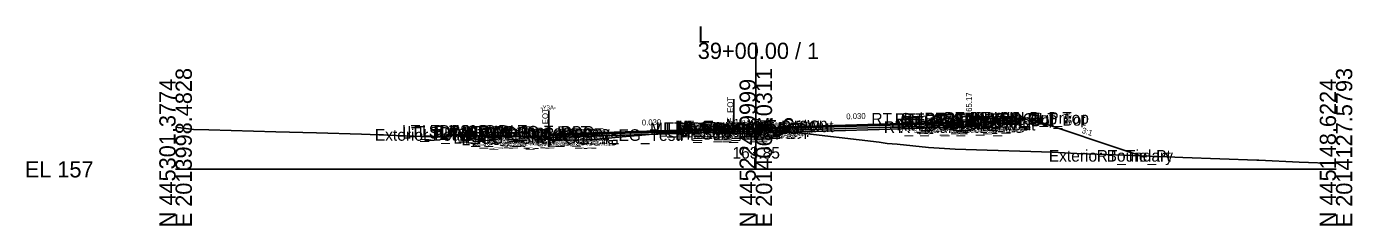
# Model space of a CAD drawing. Extents: x -26 to 4203, y -10 to 9526.
# Drawn here: x 1974.3 to 2202.8, y 8990.3 to 9024.6 of the extents above; entities that cross this region are included whole.
import ezdxf

# ---------------------------------------------------------------- set-up
doc = ezdxf.new("R2010")
doc.units = 0
for name, color, linetype in [('Default', 7, 'Continuous'), ('Exist CMT Pavement', 7, 'Continuous'), ('Exist Cross Section Cell', 7, 'Continuous'), ('Exist XS Center Line Elevation Label', 7, 'Continuous'), ('Exist XS Ground Line', 7, 'Continuous'), ('Prop CMT Conc Surface', 7, 'Continuous'), ('Prop CMT Concrete Structures', 7, 'Continuous'), ('Prop CMT Pvmt Course 1', 7, 'Continuous'), ('Prop CMT Pvmt Course 1 CG', 7, 'Continuous'), ('Prop CMT Pvmt Course 1 Wedge', 7, 'Continuous'), ('Prop CMT Pvmt Course 2', 7, 'Continuous'), ('Prop CMT Pvmt Course 2 Wedge', 7, 'Continuous'), ('Prop CMT Pvmt Course 3', 7, 'Continuous'), ('Prop CMT Pvmt Course 3 Wedge', 7, 'Continuous'), ('Prop CMT Pvmt Surface', 7, 'Continuous'), ('Prop CMT Pvmt Wedge Surface 1', 7, 'Continuous'), ('Prop CMT Pvmt Wedge Surface 2', 7, 'Continuous'), ('Prop CMT Pvmt Wedge Surface 3', 7, 'Continuous'), ('Prop CMT Shear Line', 7, 'Continuous'), ('Prop CMT Shear Line Text', 7, 'Continuous'), ('Prop CMT Slope Grass', 7, 'Continuous'), ('Prop CMT Subgrade Earthwork', 7, 'Continuous'), ('Prop XS Hydro Elevations', 7, 'Continuous'), ('Prop XS Label Text', 7, 'Continuous'), ('Prop XS SE Text', 7, 'Continuous'), ('Prop XS Side Slope Text', 7, 'Continuous'), ('Scratch_Level_0', 7, 'Continuous')]:
    doc.layers.add(name, color=color, linetype=linetype)

msp = doc.modelspace()

# ---------------------------------------------------------------- linework, layer by layer
at = {"layer": 'Exist CMT Pavement'}
for p, q in [((2086.78, 9006.43), (2090.05, 9006.68)), ((2090.05, 9006.68), (2090.65, 9006.73)), ((2090.65, 9006.73), (2092.1, 9006.81)), ((2092.1, 9006.81), (2093.35, 9006.9)), ((2093.35, 9006.9), (2094.49, 9006.97)), ((2094.49, 9006.97), (2095.82, 9007.06)), ((2095.82, 9007.06), (2096.21, 9007.08)), ((2064.31, 9005.13), (2068.53, 9005.01)), ((2068.53, 9005.01), (2069.19, 9005.04)), ((2069.19, 9005.04), (2072.26, 9005.15)), ((2072.26, 9005.15), (2076.98, 9005.61)), ((2076.98, 9005.61), (2079.7, 9005.86)), ((2079.7, 9005.86), (2082.91, 9006.13)), ((2082.91, 9006.13), (2084.39, 9006.25)), ((2084.39, 9006.25), (2086.78, 9006.43))]:
    msp.add_line(p, q, dxfattribs=at)
at = {"layer": 'Exist Cross Section Cell'}
for p, q in [((2100, 9000), (2100, 9021.84)), ((2000, 9000), (2100, 9000)), ((2100, 9000), (2200, 9000))]:
    msp.add_line(p, q, dxfattribs=at)
at = {"layer": 'Exist XS Ground Line'}
msp.add_lwpolyline([(2000, 9007.27), (2000.45, 9007.24), (2003.07, 9006.89), (2005.73, 9006.8), (2017.27, 9006.46), (2024.29, 9006.31), (2032.07, 9006.07), (2044.07, 9005.63), (2046.22, 9005.6), (2047.29, 9006.04), (2049.47, 9005.96), (2049.86, 9005.95), (2052.76, 9005.79), (2055.69, 9005.74), (2058.39, 9005.72), (2059.49, 9005.71), (2061.04, 9005.68), (2061.51, 9005.51), (2061.98, 9005.18), (2062.57, 9005.18), (2068.53, 9005.01), (2069.19, 9005.04), (2072.26, 9005.15), (2072.61, 9005.19), (2073.71, 9005.3), (2075.16, 9005.44), (2076.16, 9005.53), (2076.98, 9005.61), (2079.04, 9005.8), (2079.7, 9005.86), (2080.26, 9005.91), (2081.49, 9006.02), (2082.91, 9006.13), (2083.45, 9006.18), (2084.39, 9006.25), (2086.78, 9006.43), (2088.56, 9006.57), (2090.05, 9006.68), (2090.65, 9006.73), (2092.1, 9006.81), (2093.35, 9006.9), (2094.49, 9006.97), (2095.82, 9007.06), (2096.22, 9007.08), (2100, 9006.85), (2104.52, 9006.58), (2105.69, 9006.51), (2106.48, 9006.41), (2121.24, 9004.66), (2122.67, 9004.46), (2124.36, 9004.34), (2129.77, 9003.79), (2134.34, 9003.48), (2139.86, 9003.28), (2147.43, 9003.08), (2151.06, 9002.95), (2155.35, 9002.74), (2160.52, 9002.53), (2170.85, 9002.18), (2173.62, 9002.06), (2186.34, 9001.58), (2186.71, 9001.56), (2193.64, 9001.23), (2200, 9001.01)], dxfattribs=at)
at = {"layer": 'Prop CMT Conc Surface'}
for points in [[(2141.25, 9008.77), (2146.25, 9008.86)], [(2134.75, 9008.19), (2136.75, 9008.17)], [(2136.75, 9008.17), (2136.75, 9008.67), (2137.25, 9008.67)]]:
    msp.add_lwpolyline(points, dxfattribs=at)
at = {"layer": 'Prop CMT Concrete Structures'}
for points in [[(2146.25, 9008.86), (2141.25, 9008.77)], [(2141.25, 9008.77), (2141.25, 9008.43)], [(2146.25, 9008.53), (2146.25, 9008.86)], [(2094.5, 9006.99), (2094.49, 9007.15), (2093.74, 9007.4), (2093, 9007.42), (2092.26, 9007.31), (2091.51, 9007.06), (2091.5, 9006.9)], [(2091.5, 9006.9), (2094.5, 9006.99)], [(2108.62, 9007.41), (2108.61, 9007.58), (2107.86, 9007.83), (2107.12, 9007.84), (2106.38, 9007.74), (2105.63, 9007.49), (2105.62, 9007.32)], [(2105.62, 9007.32), (2108.62, 9007.41)], [(2134.75, 9008.19), (2136.75, 9008.17), (2136.75, 9008.67), (2137.25, 9008.67)], [(2137.25, 9008.67), (2137.25, 9007.69), (2134.75, 9007.61)], [(2134.75, 9007.61), (2134.75, 9008.19)], [(2141.25, 9008.43), (2146.25, 9008.53)]]:
    msp.add_lwpolyline(points, dxfattribs=at)
at = {"layer": 'Prop CMT Pvmt Course 1'}
for points in [[(2100, 9007.15), (2064.31, 9006.08)], [(2064.31, 9005.96), (2096.22, 9006.91)], [(2096.22, 9006.91), (2096.22, 9006.79)], [(2096.22, 9006.79), (2100, 9006.9)], [(2100, 9007.15), (2134.75, 9008.19)], [(2134.75, 9007.94), (2100, 9006.9)], [(2100, 9006.9), (2100, 9007.15)], [(2100, 9006.9), (2100, 9007.15)], [(2134.75, 9008.19), (2134.75, 9007.94)], [(2064.31, 9006.08), (2064.31, 9005.83)], [(2064.31, 9005.83), (2064.31, 9005.96)], [(2064.31, 9005.83), (2064.31, 9005.83)]]:
    msp.add_lwpolyline(points, dxfattribs=at)
msp.add_lwpolyline([(2100, 9006.9), (2100, 9007.03), (2100, 9007.03), (2100, 9006.9)], close=True, dxfattribs=at)
at = {"layer": 'Prop CMT Pvmt Course 1 CG'}
for points in [[(2134.75, 9007.61), (2137.75, 9007.7), (2138.07, 9007.38)], [(2134.75, 9007.28), (2134.75, 9007.61)], [(2138.07, 9007.38), (2134.75, 9007.28)], [(2064.31, 9005.08), (2064.31, 9005.5)]]:
    msp.add_lwpolyline(points, dxfattribs=at)
at = {"layer": 'Prop CMT Pvmt Course 1 Wedge'}
for points in [[(2064.31, 9005.96), (2068.53, 9006.08), (2069.19, 9006.1), (2072.26, 9006.19), (2072.61, 9006.21), (2073.71, 9006.24), (2075.16, 9006.28), (2076.16, 9006.31), (2076.98, 9006.34), (2079.04, 9006.4), (2079.7, 9006.42), (2080.26, 9006.43), (2081.49, 9006.47), (2082.91, 9006.51), (2083.45, 9006.53), (2084.39, 9006.56), (2084.58, 9006.56), (2086.78, 9006.63), (2086.78, 9006.63), (2086.78, 9006.63), (2088.56, 9006.68), (2090.05, 9006.73), (2090.65, 9006.75), (2091.35, 9006.77)], [(2091.35, 9006.77), (2090.65, 9006.73), (2090.05, 9006.68), (2088.56, 9006.57), (2088.41, 9006.55), (2086.78, 9006.51), (2086.78, 9006.51), (2086.78, 9006.51), (2084.58, 9006.44), (2084.39, 9006.43), (2083.45, 9006.41), (2082.91, 9006.39), (2081.49, 9006.35), (2080.26, 9006.31), (2079.7, 9006.29), (2079.04, 9006.27), (2076.98, 9006.21), (2076.16, 9006.19), (2075.16, 9006.16), (2073.71, 9006.11), (2072.61, 9006.08), (2072.26, 9006.07), (2069.19, 9005.98), (2068.53, 9005.96), (2064.31, 9005.83)], [(2064.31, 9005.83), (2064.31, 9005.96)]]:
    msp.add_lwpolyline(points, dxfattribs=at)
at = {"layer": 'Prop CMT Pvmt Course 2'}
for points in [[(2100, 9006.9), (2096.22, 9006.79)], [(2096.22, 9006.79), (2096.22, 9006.46)], [(2096.22, 9006.46), (2100, 9006.57)], [(2100, 9006.9), (2134.75, 9007.94)], [(2134.75, 9007.61), (2100, 9006.57)], [(2100, 9006.57), (2100, 9006.9)], [(2100, 9006.57), (2100, 9006.9)], [(2134.75, 9007.94), (2134.75, 9007.61)], [(2064.31, 9005.5), (2064.31, 9005.83)], [(2064.31, 9005.83), (2064.31, 9005.83)], [(2064.31, 9005.83), (2064.31, 9005.5)], [(2064.31, 9005.5), (2064.31, 9005.5)]]:
    msp.add_lwpolyline(points, dxfattribs=at)
at = {"layer": 'Prop CMT Pvmt Course 2 Wedge'}
for points in [[(2064.31, 9005.83), (2068.53, 9005.96), (2069.19, 9005.98), (2072.26, 9006.07), (2072.61, 9006.08), (2073.71, 9006.11), (2075.16, 9006.16), (2076.16, 9006.19), (2076.98, 9006.21), (2079.04, 9006.27), (2079.7, 9006.29), (2080.26, 9006.31), (2081.49, 9006.35), (2082.91, 9006.39), (2083.45, 9006.41), (2084.39, 9006.43), (2084.58, 9006.44), (2086.78, 9006.51), (2086.78, 9006.51), (2086.78, 9006.51), (2088.41, 9006.55)], [(2088.41, 9006.55), (2086.78, 9006.43), (2086.78, 9006.43), (2086.78, 9006.43), (2084.58, 9006.27), (2084.39, 9006.25), (2083.45, 9006.18), (2082.91, 9006.13), (2081.49, 9006.02), (2081.41, 9006.01), (2080.26, 9005.98), (2079.7, 9005.96), (2079.04, 9005.94), (2076.98, 9005.88), (2076.16, 9005.85), (2075.16, 9005.82), (2073.71, 9005.78), (2072.61, 9005.75), (2072.26, 9005.74), (2069.19, 9005.64), (2068.53, 9005.62), (2064.31, 9005.5)], [(2064.31, 9005.5), (2064.31, 9005.83)]]:
    msp.add_lwpolyline(points, dxfattribs=at)
at = {"layer": 'Prop CMT Pvmt Course 3'}
for points in [[(2100, 9006.57), (2096.22, 9006.46)], [(2100, 9006.57), (2134.75, 9007.61)], [(2134.75, 9007.28), (2100, 9006.24)], [(2100, 9006.24), (2100, 9006.57)], [(2100, 9006.24), (2100, 9006.57)], [(2134.75, 9007.61), (2134.75, 9007.28)], [(2064.31, 9005.5), (2064.31, 9005.5)], [(2064.31, 9005.5), (2064.31, 9005.13)], [(2064.31, 9005.17), (2064.31, 9005.5)], [(2096.22, 9006.46), (2096.22, 9006.12)], [(2096.22, 9006.12), (2100, 9006.24)]]:
    msp.add_lwpolyline(points, dxfattribs=at)
at = {"layer": 'Prop CMT Pvmt Course 3 Wedge'}
for points in [[(2064.31, 9005.5), (2068.53, 9005.62), (2069.19, 9005.64), (2072.26, 9005.74), (2072.61, 9005.75), (2073.71, 9005.78), (2075.16, 9005.82), (2076.16, 9005.85), (2076.98, 9005.88), (2079.04, 9005.94), (2079.7, 9005.96), (2080.26, 9005.98), (2081.42, 9006.01)], [(2081.42, 9006.01), (2080.26, 9005.91), (2079.7, 9005.86), (2079.04, 9005.8), (2076.98, 9005.61), (2076.16, 9005.53), (2075.16, 9005.44), (2073.71, 9005.3), (2072.61, 9005.19), (2072.26, 9005.15), (2069.19, 9005.04), (2068.53, 9005.01), (2064.31, 9005.13)], [(2064.31, 9005.13), (2064.31, 9005.5)]]:
    msp.add_lwpolyline(points, dxfattribs=at)
at = {"layer": 'Prop CMT Pvmt Surface'}
for points in [[(2100, 9007.15), (2064.31, 9006.08)], [(2100, 9007.15), (2134.75, 9008.19)]]:
    msp.add_lwpolyline(points, dxfattribs=at)
at = {"layer": 'Prop CMT Pvmt Wedge Surface 1'}
for points in [[(2096.22, 9006.91), (2064.31, 9005.96)], [(2096.22, 9006.79), (2096.22, 9006.91)], [(2100, 9006.9), (2096.22, 9006.79)], [(2100, 9007.15), (2100, 9006.9)], [(2064.31, 9005.83), (2064.31, 9006.08)], [(2064.31, 9005.96), (2064.31, 9005.83)], [(2064.31, 9005.83), (2064.31, 9005.83)]]:
    msp.add_lwpolyline(points, dxfattribs=at)
at = {"layer": 'Prop CMT Pvmt Wedge Surface 2'}
for points in [[(2100, 9006.9), (2064.31, 9005.83)], [(2100, 9007.15), (2100, 9006.9)], [(2064.31, 9005.83), (2064.31, 9006.08)]]:
    msp.add_lwpolyline(points, dxfattribs=at)
at = {"layer": 'Prop CMT Pvmt Wedge Surface 3'}
for points in [[(2100, 9006.57), (2064.31, 9005.5)], [(2100, 9007.15), (2100, 9006.57)], [(2064.31, 9005.5), (2064.31, 9006.08)]]:
    msp.add_lwpolyline(points, dxfattribs=at)
at = {"layer": 'Prop CMT Shear Line'}
msp.add_line((2064.31, 9003.91), (2064.31, 9010.13), dxfattribs=at)
at = {"layer": 'Prop CMT Slope Grass'}
for points in [[(2137.25, 9008.67), (2146.75, 9008.86)], [(2146.75, 9008.86), (2166.36, 9002.33)]]:
    msp.add_lwpolyline(points, dxfattribs=at)
at = {"layer": 'Prop CMT Subgrade Earthwork'}
msp.add_line((2064.31, 9006.08), (2064.31, 9005.13), dxfattribs=at)
for points in [[(2100, 9006.24), (2096.22, 9006.12), (2096.21, 9007.08)], [(2100, 9006.24), (2134.75, 9007.28)], [(2134.75, 9007.28), (2138.07, 9007.38), (2139.41, 9008.72)]]:
    msp.add_lwpolyline(points, dxfattribs=at)
at = {"layer": 'Prop XS Label Text'}
for p, q in [((2096.21, 9012.08), (2096.21, 9007.08)), ((2064.31, 9010.13), (2064.31, 9005.13))]:
    msp.add_line(p, q, dxfattribs=at)

# ---------------------------------------------------------------- texts
at = {"layer": 'Default'}
msp.add_text('-', height=0.0001, dxfattribs=at).set_placement((2000, 9000))
at = {"layer": 'Exist Cross Section Cell'}
for s, p in [('L', (2090, 9021.84)), ('39+00.00 / 1', (2090, 9019.04)), ('EL 157', (1974, 8998.6))]:
    msp.add_text(s, height=2.8, dxfattribs=at).set_placement(p)
for s, p in [('E 2013998.4828', (2002.8, 8990)), ('E 2014063.0311', (2102.8, 8990)), ('E 2014127.5793', (2202.8, 8990)), ('N 445301.3774', (2000, 8990)), ('N 445224.9999', (2100, 8990)), ('N 445148.6224', (2200, 8990))]:
    msp.add_text(s, height=2.8, rotation=90, dxfattribs=at).set_placement(p)
at = {"layer": 'Exist XS Center Line Elevation Label'}
msp.add_text('163.85', height=2, dxfattribs=at).set_placement((2095.98, 9001.85))
at = {"layer": 'Prop CMT Shear Line Text'}
msp.add_text('-Y3A-', height=0.75, dxfattribs=at).set_placement((2062.9, 9010.28))
at = {"layer": 'Prop XS Hydro Elevations'}
msp.add_text('165.17', height=1, rotation=90, dxfattribs=at).set_placement((2137.25, 9009.17))
at = {"layer": 'Prop XS Label Text'}
for p in [(2096.11, 9008.11), (2064.21, 9006.15)]:
    msp.add_text('E. EOT', height=1, rotation=90, dxfattribs=at).set_placement(p)
at = {"layer": 'Prop XS SE Text'}
for rotation, p in [(1.7192, (2115.6, 9008.62)), (1.7186, (2080.37, 9007.56))]:
    msp.add_text('0.030', height=1, rotation=rotation, dxfattribs=at).set_placement(p)
at = {"layer": 'Prop XS Side Slope Text'}
msp.add_text('3:1', height=1, rotation=341.5651, dxfattribs=at).set_placement((2156.09, 9006.31))
at = {"layer": 'Scratch_Level_0'}
for s, p in [('MI_Crown', (2100.19, 9006.84)), ('RT_Sub_Trench_Out_DLT', (2119.93, 9007.72)), ('RT_CG_Top_Face', (2123.96, 9007.67)), ('RT_CG1_Shelf_Out', (2124.25, 9006.7)), ('RT_PV2_OEOT', (2124.88, 9006.94)), ('RT_CG_Top_Gut', (2124.94, 9007.17)), ('RT_PV1_OEOT', (2125.44, 9007.19)), ('RT_CG_Top_BOC', (2125.49, 9007.67)), ('RT_SDWK_In_Top', (2129.06, 9007.77)), ('RT_SDWK_In_Bot', (2129.09, 9007.43)), ('RT_SDWK_Out_Top', (2132.44, 9007.86)), ('RT_SDWK_Out_Bot', (2132.47, 9007.53)), ('RT_CSLP_Pnt', (2136.88, 9007.86)), ('Exterior Boundary', (2034.34, 9004.93)), ('LT_SDWK_Out_Top', (2039.04, 9005.63)), ('LT_SDWK_Out_Bot', (2039.07, 9005.3)), ('LT_Sub_Trench_Out_DLT', (2039.93, 9005.49)), ('LT_CSLP_Pnt', (2042.48, 9005.63)), ('LT_Tie_Pt', (2042.64, 9004.93)), ('LT_SDWK_In_Top', (2045.66, 9005.53)), ('LT_SDWK_In_Bot', (2045.69, 9005.2)), ('LT_CG1_Shelf_Out', (2047.86, 9004.41)), ('LT_CG_Top_Face', (2049.56, 9005.44)), ('LT_CG_Top_BOC', (2050.09, 9005.44)), ('LT_CG_Top_Gut', (2050.54, 9004.94)), ('LT_PV2_OEEOP', (2053.61, 9004.83)), ('LT_PV3_OEEOP', (2053.61, 9004.5)), ('LT_PV1_OEEOP', (2054.18, 9004.96)), ('LT_CG_Bot_IE', (2054.22, 9004.5)), ('LT_PV2_OEOT', (2054.48, 9004.83)), ('LT_PV3_OEOT', (2054.48, 9004.5)), ('LT_PV1_OEOT', (2055.05, 9005.08)), ('LT_PV_EG_TestPt', (2066.67, 9004.91)), ('MI_Face Out', (2081.78, 9006.06)), ('LT_PV_Sub_Tie_In', (2082.77, 9006.08)), ('LT_PV_IEEOP_EG', (2084.41, 9006.08)), ('MI_Crown', (2086.07, 9006.39)), ('LT_Sub_IEEOP', (2086.08, 9005.12)), ('LT_PV2_IEEOP', (2086.17, 9005.79)), ('LT_PV3_IEEOP', (2086.17, 9005.46)), ('MI_Crown', (2086.2, 9006.39)), ('MI_Face In', (2086.38, 9006.15)), ('MI_Top In', (2086.59, 9006.4)), ('LT_PV1_IEEOP', (2086.74, 9005.91)), ('MI_Bot In', (2087.38, 9005.99)), ('RT_Sub_OEEOP', (2089.17, 9005.24)), ('RT_PV2_OEEOP', (2089.26, 9005.9)), ('RT_PV3_OEEOP', (2089.26, 9005.57)), ('RT_PV1_OEEOP', (2089.83, 9006.03)), ('RT_PV2_IEEOP', (2089.91, 9005.9)), ('RT_PV1_IEEOP', (2090.47, 9006.03)), ('LT_Sub_PGL', (2091.12, 9005.24)), ('RT_PV2_PGL', (2091.17, 9005.9)), ('LT_PV2_PGL', (2091.21, 9005.9)), ('LT_PV3_PGL', (2091.21, 9005.57)), ('RT_PV1_PGL', (2091.73, 9006.15)), ('LT_PV1_PGL', (2091.78, 9006.15)), ('MI_Top Out', (2094.83, 9006.69)), ('MI_Face In', (2096.04, 9006.44)), ('MI_Face In', (2097.52, 9006.49)), ('MI_Bot Out', (2099.88, 9006.41)), ('RT_Sub_OEOT_CG', (2122.07, 9006.28)), ('RT_CG_Bot_IE', (2124.62, 9006.61)), ('RT_Sub_OEOT', (2124.78, 9006.28)), ('RT_PV3_OEOT', (2124.88, 9006.61)), ('RT_CG_Bot_BOC', (2125.52, 9006.69)), ('RT_Sub_OEOP', (2128.14, 9006.38)), ('LT_PV_Sub_Tie_Out', (2049.27, 9004.13)), ('LT_CG_Bot_BOC', (2050.12, 9004.42)), ('LT_Sub_OEOP', (2050.99, 9003.98)), ('LT_Sub_OEOT_CG', (2051.68, 9004.08)), ('LT_PV_OEEOP_EG', (2051.85, 9004.13)), ('LT_Sub_OEEOP', (2053.52, 9004.17)), ('LT_Sub_OEOT', (2054.38, 9004.17)), ('Exterior Boundary', (2150.5, 9001.33)), ('RT_Tie_Pt', (2158.75, 9001.33))]:
    msp.add_text(s, height=2, dxfattribs=at).set_placement(p)

doc.saveas('drawing.dxf')
